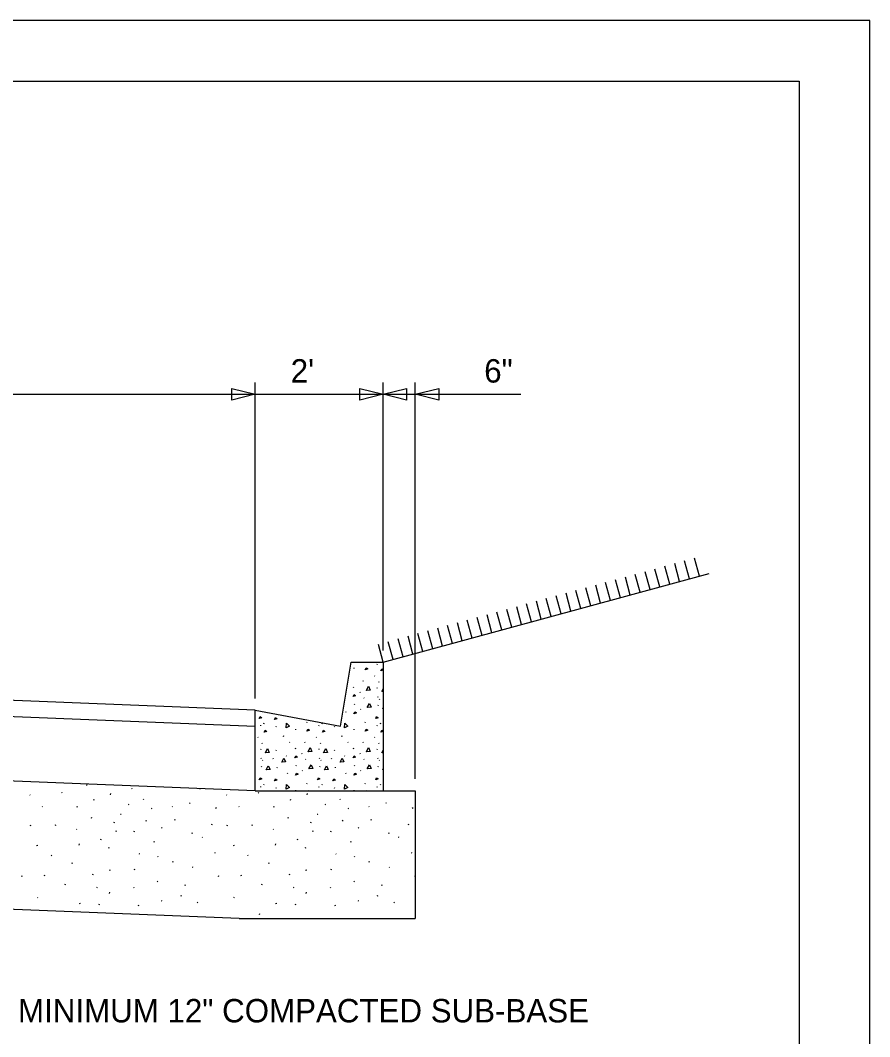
# Model space of a CAD drawing. Extents: x 29.7 to 46.4, y -39.2 to -28.2.
# Drawn here: x 43.008 to 46.033, y -31.812 to -28.193 of the extents above; entities that cross this region are included whole.
import ezdxf

# ---------------------------------------------------------------- set-up
doc = ezdxf.new("R2010")
doc.units = 0
for name, color, linetype in [('Level 11', 7, 'Continuous'), ('Level 6', 7, 'Continuous'), ('Level 60', 7, 'Continuous')]:
    doc.layers.add(name, color=color, linetype=linetype)

msp = doc.modelspace()

# ---------------------------------------------------------------- linework, layer by layer
at = {"layer": 'Level 11'}
for p, q in [((43.845, -30.6078), (43.845, -29.4825)), ((44.3007, -30.437), (44.3007, -29.4825)), ((44.4146, -30.8942), (44.4146, -29.4825)), ((38.3762, -29.5241), (43.845, -29.5241)), ((43.5533, -29.5241), (44.5924, -29.5241)), ((44.009, -29.5241), (44.791, -29.5241))]:
    msp.add_line(p, q, dxfattribs=at)
for points in [[(43.7616, -29.5033), (43.845, -29.5241), (43.7616, -29.545)], [(43.7616, -29.5033), (43.845, -29.5241), (43.7616, -29.545)], [(44.2174, -29.5033), (44.3007, -29.5241), (44.2174, -29.545)], [(44.384, -29.545), (44.3007, -29.5241), (44.384, -29.5033)], [(44.498, -29.545), (44.4146, -29.5241), (44.498, -29.5033)]]:
    msp.add_lwpolyline(points, close=True, dxfattribs=at)
at = {"layer": 'Level 6'}
for p, q in [((45.4263, -30.172), (45.4089, -30.1081)), ((45.2856, -30.2103), (45.2682, -30.1465)), ((45.3208, -30.2007), (45.3034, -30.1369)), ((45.356, -30.1912), (45.3386, -30.1273)), ((45.3912, -30.1816), (45.3738, -30.1177)), ((44.3007, -30.4786), (45.4607, -30.1626)), ((45.1449, -30.2487), (45.1275, -30.1848)), ((45.1801, -30.2391), (45.1627, -30.1752)), ((45.2153, -30.2295), (45.1979, -30.1656)), ((45.2505, -30.2199), (45.2331, -30.1561)), ((45.0394, -30.2774), (45.022, -30.2135)), ((45.0746, -30.2678), (45.0572, -30.2039)), ((45.1097, -30.2582), (45.0923, -30.1944)), ((44.8987, -30.3157), (44.8813, -30.2519)), ((44.9339, -30.3061), (44.9165, -30.2423)), ((44.969, -30.2966), (44.9516, -30.2327)), ((45.0042, -30.287), (44.9868, -30.2231)), ((44.758, -30.3541), (44.7406, -30.2902)), ((44.7932, -30.3445), (44.7758, -30.2806)), ((44.8284, -30.3349), (44.811, -30.271)), ((44.8635, -30.3253), (44.8461, -30.2614)), ((44.6173, -30.3924), (44.5999, -30.3285)), ((44.6524, -30.3828), (44.635, -30.3189)), ((44.6876, -30.3732), (44.6702, -30.3094)), ((44.7228, -30.3636), (44.7054, -30.2998)), ((44.5118, -30.4211), (44.4944, -30.3573)), ((44.5469, -30.4116), (44.5295, -30.3477)), ((44.5821, -30.402), (44.5647, -30.3381)), ((44.3711, -30.4594), (44.3537, -30.3956)), ((44.4062, -30.4499), (44.3888, -30.386)), ((44.4414, -30.4403), (44.424, -30.3764)), ((44.4766, -30.4307), (44.4592, -30.3669)), ((44.3007, -30.4786), (44.2833, -30.4148)), ((44.3359, -30.469), (44.3185, -30.4052)), ((44.1488, -30.7065), (44.1868, -30.4786)), ((44.1868, -30.4786), (44.3007, -30.4786)), ((44.1953, -30.4979), (44.1956, -30.5005)), ((44.2794, -30.487), (44.2805, -30.4845)), ((44.291, -30.479), (44.2912, -30.4786)), ((44.3007, -30.5063), (44.2916, -30.5091)), ((44.3007, -30.4786), (44.3007, -30.9358)), ((43.845, -30.6495), (41.1106, -30.5401)), ((44.1755, -30.5461), (44.1755, -30.5462)), ((44.2281, -30.5437), (44.2292, -30.5456)), ((44.2695, -30.5265), (44.2707, -30.5282)), ((44.1952, -30.5681), (44.1964, -30.5655)), ((44.2795, -30.5711), (44.2806, -30.5685)), ((44.2834, -30.5475), (44.2846, -30.5492)), ((44.2959, -30.5825), (44.3007, -30.5735)), ((44.3007, -30.5821), (44.2963, -30.5825)), ((43.845, -30.7068), (41.1106, -30.5974)), ((44.2169, -30.584), (44.218, -30.5857)), ((44.2309, -30.6051), (44.2321, -30.6069)), ((44.2799, -30.6006), (44.2811, -30.6025)), ((44.2861, -30.6088), (44.2873, -30.6106)), ((43.845, -30.6495), (44.1488, -30.7065)), ((43.845, -30.9358), (43.845, -30.6495)), ((44.1658, -30.6544), (44.167, -30.6562)), ((44.1981, -30.6295), (44.1991, -30.6269)), ((44.2196, -30.6454), (44.2208, -30.647)), ((44.2823, -30.6324), (44.2834, -30.6298)), ((44.2988, -30.6438), (44.3007, -30.6403)), ((44.3007, -30.6437), (44.299, -30.6438)), ((44.0282, -30.6936), (44.0293, -30.691)), ((44.2358, -30.6936), (44.2369, -30.691)), ((43.8643, -30.7053), (43.8653, -30.7028)), ((43.8758, -30.6973), (43.877, -30.6947)), ((43.9195, -30.709), (43.9206, -30.7065)), ((43.9877, -30.7162), (43.9881, -30.7189)), ((44.0718, -30.7053), (44.0729, -30.7028)), ((44.0834, -30.6973), (44.0846, -30.6947)), ((44.1271, -30.709), (44.1282, -30.7065)), ((44.1953, -30.7162), (44.1956, -30.7189)), ((44.2794, -30.7053), (44.2805, -30.7028)), ((44.291, -30.6973), (44.2922, -30.6947)), ((44.3007, -30.7246), (44.2916, -30.7274)), ((43.8543, -30.7448), (43.8555, -30.7465)), ((43.9456, -30.7424), (43.9467, -30.7397)), ((43.9668, -30.7626), (43.9679, -30.7645)), ((44.0205, -30.7621), (44.0216, -30.7639)), ((44.0619, -30.7448), (44.0631, -30.7465)), ((44.1532, -30.7424), (44.1543, -30.7397)), ((44.1744, -30.7626), (44.1755, -30.7645)), ((44.2281, -30.7621), (44.2292, -30.7639)), ((44.2695, -30.7448), (44.2707, -30.7465)), ((43.8644, -30.7894), (43.8654, -30.7868)), ((43.8682, -30.7658), (43.8694, -30.7675)), ((43.9196, -30.793), (43.9207, -30.7905)), ((43.9876, -30.7864), (43.9888, -30.7838)), ((44.0719, -30.7894), (44.073, -30.7868)), ((44.0758, -30.7658), (44.077, -30.7675)), ((44.1272, -30.793), (44.1283, -30.7905)), ((44.1952, -30.7864), (44.1964, -30.7838)), ((44.2795, -30.7894), (44.2806, -30.7868)), ((44.2834, -30.7658), (44.2846, -30.7675)), ((44.2959, -30.8008), (44.3007, -30.7918)), ((43.845, -30.9358), (41.1106, -30.8264)), ((43.8647, -30.8189), (43.8659, -30.8208)), ((43.8709, -30.8271), (43.8721, -30.8289)), ((43.9073, -30.8205), (43.9085, -30.8222)), ((43.9555, -30.8114), (43.9567, -30.8131)), ((44.0093, -30.8023), (44.0104, -30.8041)), ((44.0233, -30.8234), (44.0245, -30.8252)), ((44.0723, -30.8189), (44.0735, -30.8208)), ((44.0785, -30.8271), (44.0797, -30.8289)), ((44.1149, -30.8205), (44.1161, -30.8222)), ((44.1631, -30.8114), (44.1643, -30.8131)), ((44.2169, -30.8023), (44.218, -30.8041)), ((44.2309, -30.8234), (44.2321, -30.8252)), ((44.2799, -30.8189), (44.2811, -30.8208)), ((44.2861, -30.8271), (44.2873, -30.8289)), ((44.3007, -30.8004), (44.2963, -30.8008)), ((43.8671, -30.8508), (43.8682, -30.8481)), ((43.9224, -30.8544), (43.9235, -30.8517)), ((43.9905, -30.8478), (43.9916, -30.8452)), ((44.012, -30.8637), (44.0132, -30.8653)), ((44.0747, -30.8508), (44.0758, -30.8481)), ((44.13, -30.8544), (44.1311, -30.8517)), ((44.1981, -30.8478), (44.1991, -30.8452)), ((44.2196, -30.8637), (44.2208, -30.8653)), ((44.2823, -30.8508), (44.2834, -30.8481)), ((44.2988, -30.8621), (44.3007, -30.8586)), ((44.3007, -30.862), (44.299, -30.8621)), ((43.9582, -30.8727), (43.9594, -30.8745)), ((44.1658, -30.8727), (44.167, -30.8745)), ((43.1574, -30.9446), (43.1556, -30.9427)), ((43.2446, -30.9168), (43.2458, -30.9131)), ((43.4067, -30.9301), (43.4049, -30.9283)), ((43.6498, -30.9289), (43.646, -30.9297)), ((43.845, -30.9358), (44.4146, -30.9358)), ((43.8574, -30.9446), (43.8556, -30.9427)), ((43.8643, -30.9236), (43.8653, -30.9211)), ((43.8758, -30.9156), (43.877, -30.913)), ((43.9195, -30.9273), (43.9206, -30.9248)), ((43.9877, -30.9345), (43.9879, -30.9358)), ((44.0282, -30.9119), (44.0293, -30.9093)), ((44.0718, -30.9236), (44.0729, -30.9211)), ((44.0834, -30.9156), (44.0846, -30.913)), ((44.1271, -30.9273), (44.1282, -30.9248)), ((44.1953, -30.9345), (44.1955, -30.9358)), ((44.2358, -30.9119), (44.2369, -30.9093)), ((44.2794, -30.9236), (44.2805, -30.9211)), ((44.291, -30.9156), (44.2922, -30.913)), ((44.4146, -30.9358), (44.4146, -31.3916)), ((43.0439, -30.9519), (43.0421, -30.9501)), ((43.27, -30.9693), (43.2713, -30.9656)), ((43.3295, -30.9501), (43.3307, -30.9464)), ((43.4486, -30.9683), (43.4468, -30.9664)), ((43.6126, -30.981), (43.6108, -30.9792)), ((43.7439, -30.9519), (43.7421, -30.9501)), ((43.97, -30.9693), (43.9713, -30.9656)), ((44.0295, -30.9501), (44.0307, -30.9464)), ((44.1486, -30.9683), (44.1468, -30.9664)), ((44.3126, -30.981), (44.3108, -30.9792)), ((43.0876, -30.9937), (43.0858, -30.9919)), ((43.2107, -30.9946), (43.2119, -30.991)), ((43.3958, -30.9865), (43.3939, -30.9846)), ((43.4778, -31.001), (43.4759, -30.9992)), ((43.5507, -30.9937), (43.5488, -30.9919)), ((43.7074, -30.9974), (43.7038, -30.9992)), ((43.7876, -30.9937), (43.7858, -30.9919)), ((43.9107, -30.9946), (43.9119, -30.991)), ((44.0958, -30.9865), (44.0939, -30.9846)), ((44.1778, -31.001), (44.1759, -30.9992)), ((44.2507, -30.9937), (44.2488, -30.9919)), ((44.4074, -30.9974), (44.4038, -30.9992)), ((43.2616, -31.034), (43.2628, -31.0304)), ((43.343, -31.0509), (43.3442, -31.0473)), ((43.3651, -31.0192), (43.3666, -31.02)), ((43.3666, -31.02), (43.3673, -31.0209)), ((43.4561, -31.0441), (43.4573, -31.0405)), ((43.5579, -31.0408), (43.5591, -31.0371)), ((43.9616, -31.034), (43.9628, -31.0304)), ((44.043, -31.0509), (44.0442, -31.0473)), ((44.0651, -31.0192), (44.0666, -31.02)), ((44.0666, -31.02), (44.0673, -31.0209)), ((44.1561, -31.0441), (44.1573, -31.0405)), ((44.2579, -31.0408), (44.2591, -31.0371)), ((43.0444, -31.0616), (43.0456, -31.058)), ((43.1346, -31.0585), (43.1309, -31.0593)), ((43.21, -31.0742), (43.2082, -31.0724)), ((43.3498, -31.0814), (43.3511, -31.0778)), ((43.4136, -31.0819), (43.4149, -31.0783)), ((43.5131, -31.0691), (43.5113, -31.0673)), ((43.6206, -31.0887), (43.6218, -31.0851)), ((43.6902, -31.0577), (43.6914, -31.0541)), ((43.7444, -31.0616), (43.7456, -31.058)), ((43.8346, -31.0585), (43.8309, -31.0593)), ((43.91, -31.0742), (43.9082, -31.0724)), ((44.0498, -31.0814), (44.0511, -31.0778)), ((44.1136, -31.0819), (44.1149, -31.0783)), ((44.2131, -31.0691), (44.2113, -31.0673)), ((44.3206, -31.0887), (44.3218, -31.0851)), ((44.3902, -31.0577), (44.3914, -31.0541)), ((43.2174, -31.1293), (43.2186, -31.1257)), ((43.2955, -31.1107), (43.2967, -31.1071)), ((43.4849, -31.1192), (43.4861, -31.1156)), ((43.6573, -31.103), (43.6554, -31.1012)), ((43.9174, -31.1293), (43.9186, -31.1257)), ((43.9955, -31.1107), (43.9967, -31.1071)), ((44.1849, -31.1192), (44.1861, -31.1156)), ((44.3573, -31.103), (44.3554, -31.1012)), ((43.0702, -31.1313), (43.0664, -31.1321)), ((43.3247, -31.1397), (43.3209, -31.1406)), ((43.4333, -31.1622), (43.4315, -31.1604)), ((43.7031, -31.1588), (43.7012, -31.157)), ((43.7702, -31.1313), (43.7664, -31.1321)), ((44.0247, -31.1397), (44.0209, -31.1406)), ((44.1333, -31.1622), (44.1315, -31.1604)), ((44.4031, -31.1588), (44.4012, -31.157)), ((43.1201, -31.1673), (43.1183, -31.1655)), ((43.194, -31.1939), (43.1903, -31.1947)), ((43.4995, -31.1724), (43.4977, -31.1705)), ((43.551, -31.1903), (43.5522, -31.1866)), ((43.8201, -31.1673), (43.8183, -31.1655)), ((43.894, -31.1939), (43.8903, -31.1947)), ((44.1995, -31.1724), (44.1977, -31.1705)), ((44.251, -31.1903), (44.2522, -31.1866)), ((43.2666, -31.236), (43.2679, -31.2323)), ((43.3281, -31.2193), (43.3243, -31.2201)), ((43.4153, -31.2173), (43.4165, -31.2137)), ((43.6233, -31.2096), (43.6215, -31.2078)), ((43.9666, -31.236), (43.9679, -31.2323)), ((44.0281, -31.2193), (44.0243, -31.2201)), ((44.1153, -31.2173), (44.1165, -31.2137)), ((44.3233, -31.2096), (44.3215, -31.2078)), ((43.0139, -31.2411), (43.0151, -31.2374)), ((43.0956, -31.2379), (43.0919, -31.2387)), ((43.1683, -31.2715), (43.1695, -31.2679)), ((43.4978, -31.2604), (43.496, -31.2586)), ((43.5951, -31.2732), (43.5964, -31.2696)), ((43.7139, -31.2411), (43.7151, -31.2374)), ((43.7956, -31.2379), (43.7919, -31.2387)), ((43.8683, -31.2715), (43.8695, -31.2679)), ((44.1978, -31.2604), (44.196, -31.2586)), ((44.2951, -31.2732), (44.2964, -31.2696)), ((44.4139, -31.2411), (44.4146, -31.2388)), ((43.788, -31.3916), (41.1106, -31.2844)), ((43.2829, -31.2824), (43.2811, -31.2806)), ((43.3261, -31.3014), (43.3273, -31.2978)), ((43.414, -31.2827), (43.4122, -31.2809)), ((43.983, -31.2824), (43.9811, -31.2806)), ((44.0261, -31.3014), (44.0273, -31.2978)), ((44.114, -31.2827), (44.1122, -31.2809)), ((43.0709, -31.3179), (43.0691, -31.3161)), ((43.2212, -31.3378), (43.2174, -31.3386)), ((43.2887, -31.3426), (43.2899, -31.3389)), ((43.5131, -31.3298), (43.5113, -31.3279)), ((43.5819, -31.3107), (43.5782, -31.3115)), ((43.6403, -31.3349), (43.6385, -31.333)), ((43.7709, -31.3179), (43.7691, -31.3161)), ((43.9212, -31.3378), (43.9174, -31.3386)), ((43.9887, -31.3426), (43.9899, -31.3389)), ((44.2131, -31.3298), (44.2113, -31.3279)), ((44.2819, -31.3107), (44.2782, -31.3115)), ((44.3403, -31.3349), (44.3385, -31.333)), ((43.4304, -31.3446), (43.4267, -31.3464)), ((43.8598, -31.3764), (43.861, -31.3728)), ((44.1304, -31.3446), (44.1268, -31.3464)), ((43.788, -31.3916), (44.4146, -31.3916))]:
    msp.add_line(p, q, dxfattribs=at)
for points in [[(44.2363, -30.5055), (44.2397, -30.4982), (44.2454, -30.5025), (44.2363, -30.5055)], [(44.2916, -30.5091), (44.2951, -30.5019), (44.3007, -30.5062)], [(44.2407, -30.5789), (44.2485, -30.5642), (44.2545, -30.5777), (44.241, -30.5789)], [(44.1933, -30.6006), (44.1966, -30.5934), (44.2024, -30.5978), (44.1933, -30.6006)], [(44.196, -30.6619), (44.1995, -30.6548), (44.2052, -30.659), (44.196, -30.6619)], [(44.2434, -30.6401), (44.2512, -30.6254), (44.2573, -30.639), (44.2438, -30.6401)], [(43.8586, -30.6788), (43.8619, -30.6716), (43.8678, -30.6759), (43.8586, -30.6788)], [(43.9138, -30.6824), (43.9172, -30.6752), (43.923, -30.6796), (43.9138, -30.6824)], [(44.2738, -30.6788), (44.2771, -30.6716), (44.2829, -30.6759), (44.2738, -30.6788)], [(43.8764, -30.7274), (43.8799, -30.7202), (43.8856, -30.7245), (43.8764, -30.7274)], [(43.9545, -30.712), (43.9567, -30.6956), (43.9671, -30.7062), (43.9547, -30.712)], [(44.0288, -30.7238), (44.0321, -30.7166), (44.0378, -30.7208), (44.0288, -30.7238)], [(44.084, -30.7274), (44.0875, -30.7202), (44.0932, -30.7245), (44.084, -30.7274)], [(44.1621, -30.712), (44.1643, -30.6956), (44.1746, -30.7062), (44.1623, -30.712)], [(44.2363, -30.7238), (44.2397, -30.7166), (44.2454, -30.7208), (44.2363, -30.7238)], [(44.2916, -30.7274), (44.2951, -30.7202), (44.3007, -30.7245)], [(43.8808, -30.8008), (43.8885, -30.7861), (43.8946, -30.7997), (43.8811, -30.8008)], [(44.0331, -30.7972), (44.0409, -30.7825), (44.0469, -30.796), (44.0334, -30.7972)], [(44.0884, -30.8008), (44.0961, -30.7861), (44.1023, -30.7997), (44.0887, -30.8008)], [(44.2407, -30.7972), (44.2485, -30.7825), (44.2545, -30.796), (44.241, -30.7972)], [(43.9393, -30.8347), (43.947, -30.82), (43.9531, -30.8335), (43.9396, -30.8347)], [(43.9856, -30.8189), (43.989, -30.8117), (43.9948, -30.8161), (43.9856, -30.8189)], [(44.1469, -30.8347), (44.1546, -30.82), (44.1606, -30.8335), (44.1472, -30.8347)], [(44.1933, -30.8189), (44.1966, -30.8117), (44.2024, -30.8161), (44.1933, -30.8189)], [(43.8836, -30.8621), (43.8914, -30.8475), (43.8974, -30.8609), (43.8838, -30.8621)], [(44.0359, -30.8584), (44.0436, -30.8438), (44.0498, -30.8573), (44.0362, -30.8584)], [(44.0912, -30.8621), (44.099, -30.8475), (44.105, -30.8609), (44.0914, -30.8621)], [(44.2434, -30.8584), (44.2512, -30.8438), (44.2573, -30.8573), (44.2438, -30.8584)], [(43.8586, -30.8971), (43.8619, -30.8899), (43.8678, -30.8942), (43.8586, -30.8971)], [(43.9138, -30.9007), (43.9172, -30.8935), (43.923, -30.8979), (43.9138, -30.9007)], [(43.9884, -30.8802), (43.9919, -30.8731), (43.9976, -30.8773), (43.9884, -30.8802)], [(44.0661, -30.8971), (44.0695, -30.8899), (44.0753, -30.8942), (44.0661, -30.8971)], [(44.1214, -30.9007), (44.1248, -30.8935), (44.1306, -30.8979), (44.1214, -30.9007)], [(44.196, -30.8802), (44.1995, -30.8731), (44.2052, -30.8773), (44.196, -30.8802)], [(44.2738, -30.8971), (44.2771, -30.8899), (44.2829, -30.8942), (44.2738, -30.8971)], [(43.9545, -30.9303), (43.9567, -30.9139), (43.9671, -30.9245), (43.9547, -30.9303)], [(44.0317, -30.9358), (44.0321, -30.9349), (44.0334, -30.9358)], [(44.1621, -30.9303), (44.1643, -30.9139), (44.1746, -30.9245), (44.1623, -30.9303)], [(44.2393, -30.9358), (44.2397, -30.9349), (44.241, -30.9358)]]:
    msp.add_lwpolyline(points, dxfattribs=at)
at = {"layer": 'Level 60'}
for points in [[(29.7027, -39.1993), (46.0327, -39.1993), (46.0327, -28.1926), (29.7027, -28.1926)], [(30.3565, -28.4094), (45.7818, -28.4094), (45.7818, -38.965), (30.3565, -38.965)]]:
    msp.add_lwpolyline(points, close=True, dxfattribs=at)

# ---------------------------------------------------------------- texts
at = {"layer": 'Level 11'}
for s, p in [("2'", (43.9711, -29.4825)), ('6"', (44.6601, -29.4825))]:
    msp.add_text(s, height=0.08333, dxfattribs=at).set_placement(p)
at = {"layer": 'Level 6'}
msp.add_text('MINIMUM 12" COMPACTED SUB-BASE', height=0.083333, dxfattribs=at).set_placement((43, -31.761))

doc.saveas('drawing.dxf')
